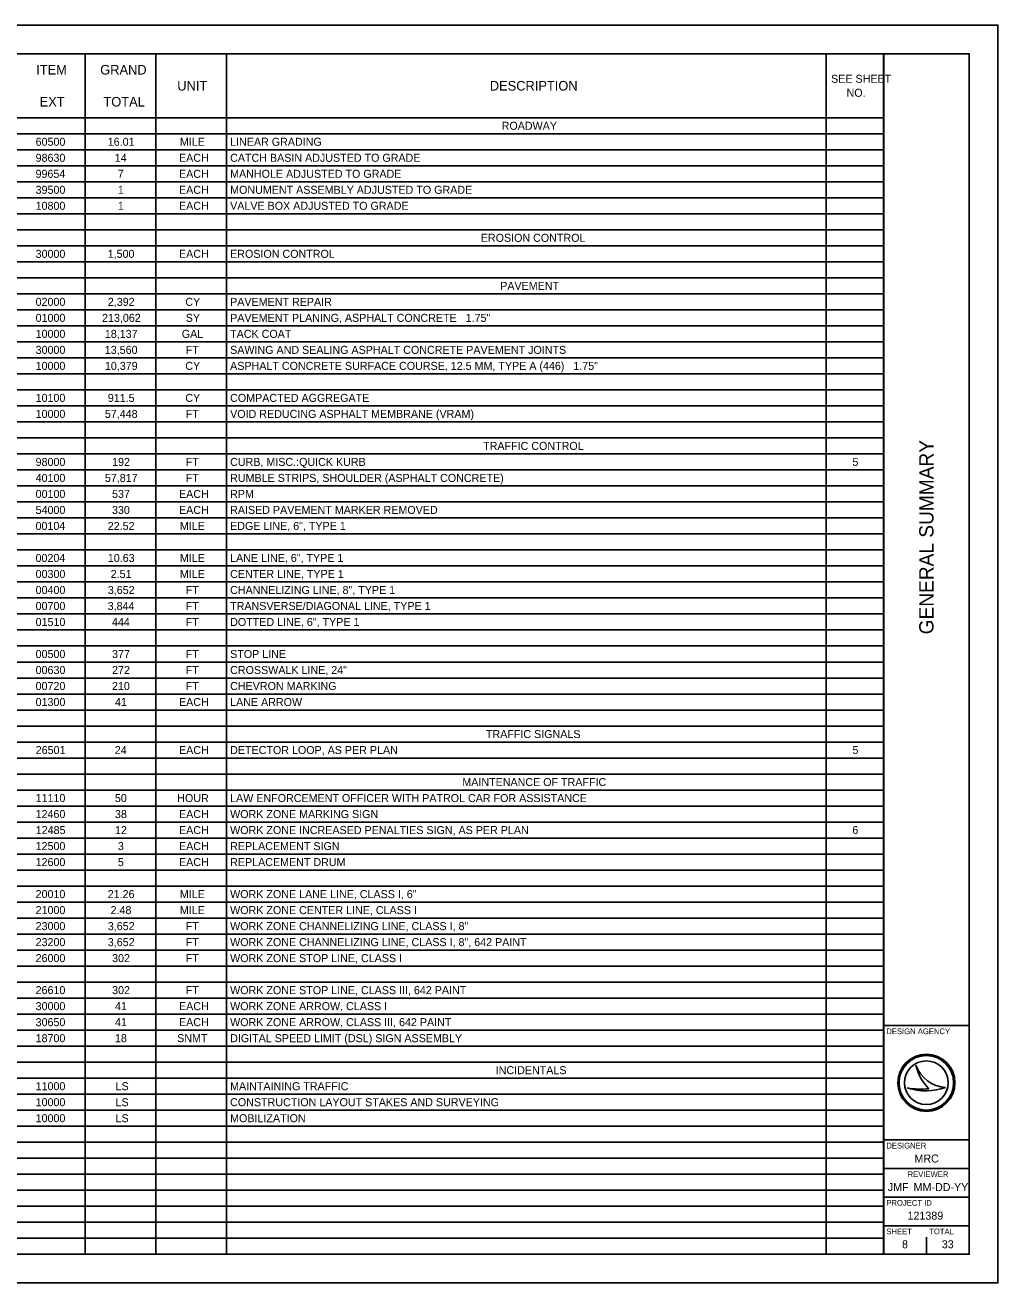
# Model space of a CAD drawing. Extents: x 0 to 34, y 0 to 22.
# Drawn here: x 16.99 to 34, y 0 to 22 of the extents above; entities that cross this region are included whole.
import ezdxf

# ---------------------------------------------------------------- set-up
doc = ezdxf.new("R2010")
doc.units = 0
for name, color, linetype in [('Default', 7, 'Continuous'), ('SH_Border', 7, 'Continuous'), ('SH_Cut_Line', 7, 'Continuous'), ('SH_Data', 7, 'Continuous')]:
    doc.layers.add(name, color=color, linetype=linetype)

msp = doc.modelspace()

# ---------------------------------------------------------------- linework, layer by layer
at = {"layer": 'SH_Border'}
for p, q in [((32, 0.5), (32, 21.5)), ((32, 4.5), (33.5, 4.5)), ((32, 2.5), (33.5, 2.5)), ((32, 2), (33.5, 2)), ((32, 1.5), (33.5, 1.5)), ((32, 1), (33.5, 1))]:
    msp.add_line(p, q, dxfattribs=at)
msp.add_lwpolyline([(1.5, 21.5), (33.5, 21.5), (33.5, 0.5), (1.5, 0.5)], close=True, dxfattribs=at)
at = {"layer": 'SH_Cut_Line'}
msp.add_lwpolyline([(0, 0), (34, 0), (34, 22), (0, 22)], close=True, dxfattribs=at)
at = {"layer": 'SH_Data'}
for p, q in [((1.5, 21.5), (32.004, 21.5)), ((18.036, 21.5), (18.036, 0.5)), ((19.272, 21.5), (19.272, 0.5)), ((20.507, 21.5), (20.507, 0.5)), ((30.999, 21.5), (30.999, 0.5)), ((32.004, 21.5), (32.004, 0.5)), ((1.5, 20.38), (32.004, 20.38)), ((1.5, 20.1), (32.004, 20.1)), ((1.5, 19.82), (32.004, 19.82)), ((1.5, 19.54), (32.004, 19.54)), ((1.5, 19.26), (32.004, 19.26)), ((1.5, 18.98), (32.004, 18.98)), ((1.5, 18.7), (32.004, 18.7)), ((1.5, 18.42), (32.004, 18.42)), ((1.5, 18.14), (32.004, 18.14)), ((1.5, 17.86), (32.004, 17.86)), ((1.5, 17.58), (32.004, 17.58)), ((1.5, 17.3), (32.004, 17.3)), ((1.5, 17.02), (32.004, 17.02)), ((1.5, 16.74), (32.004, 16.74)), ((1.5, 16.46), (32.004, 16.46)), ((1.5, 16.18), (32.004, 16.18)), ((1.5, 15.9), (32.004, 15.9)), ((1.5, 15.62), (32.004, 15.62)), ((1.5, 15.34), (32.004, 15.34)), ((1.5, 15.06), (32.004, 15.06)), ((1.5, 14.78), (32.004, 14.78)), ((1.5, 14.5), (32.004, 14.5)), ((1.5, 14.22), (32.004, 14.22)), ((1.5, 13.94), (32.004, 13.94)), ((1.5, 13.66), (32.004, 13.66)), ((1.5, 13.38), (32.004, 13.38)), ((1.5, 13.1), (32.004, 13.1)), ((1.5, 12.82), (32.004, 12.82)), ((1.5, 12.54), (32.004, 12.54)), ((1.5, 12.26), (32.004, 12.26)), ((1.5, 11.98), (32.004, 11.98)), ((1.5, 11.7), (32.004, 11.7)), ((1.5, 11.42), (32.004, 11.42)), ((1.5, 11.14), (32.004, 11.14)), ((1.5, 10.86), (32.004, 10.86)), ((1.5, 10.58), (32.004, 10.58)), ((1.5, 10.3), (32.004, 10.3)), ((1.5, 10.02), (32.004, 10.02)), ((1.5, 9.74), (32.004, 9.74)), ((1.5, 9.46), (32.004, 9.46)), ((1.5, 9.18), (32.004, 9.18)), ((1.5, 8.9), (32.004, 8.9)), ((1.5, 8.62), (32.004, 8.62)), ((1.5, 8.34), (32.004, 8.34)), ((1.5, 8.06), (32.004, 8.06)), ((1.5, 7.78), (32.004, 7.78)), ((1.5, 7.5), (32.004, 7.5)), ((1.5, 7.22), (32.004, 7.22)), ((1.5, 6.94), (32.004, 6.94)), ((1.5, 6.66), (32.004, 6.66)), ((1.5, 6.38), (32.004, 6.38)), ((1.5, 6.1), (32.004, 6.1)), ((1.5, 5.82), (32.004, 5.82)), ((1.5, 5.54), (32.004, 5.54)), ((1.5, 5.26), (32.004, 5.26)), ((1.5, 4.98), (32.004, 4.98)), ((1.5, 4.7), (32.004, 4.7)), ((1.5, 4.42), (32.004, 4.42)), ((1.5, 4.14), (32.004, 4.14)), ((1.5, 3.86), (32.004, 3.86)), ((32.567, 3.81), (32.567, 3.81)), ((1.5, 3.58), (32.004, 3.58)), ((32.417, 3.41), (32.417, 3.41)), ((32.75, 3.5), (32.75, 3.5)), ((33.087, 3.419), (33.087, 3.419)), ((1.5, 3.3), (32.004, 3.3)), ((1.5, 3.02), (32.004, 3.02)), ((1.5, 2.74), (32.004, 2.74)), ((1.5, 2.46), (32.004, 2.46)), ((1.5, 2.18), (32.004, 2.18)), ((1.5, 1.9), (32.004, 1.9)), ((1.5, 1.62), (32.004, 1.62)), ((1.5, 1.34), (32.004, 1.34)), ((1.5, 1.06), (32.004, 1.06)), ((1.5, 0.78), (32.004, 0.78)), ((32.375, 0.675), (32.375, 0.675)), ((32.75, 0.5), (32.75, 0.8)), ((1.5, 0.5), (32.004, 0.5))]:
    msp.add_line(p, q, dxfattribs=at)
for radius in [0.5, 0.477, 0.477, 0.382]:
    msp.add_circle((32.75, 3.5), radius, dxfattribs=at)
for centre, radius, start, end in [((33.116, 3.998), 0.58, 198.9257, 198.9319), ((33.347, 3.97), 0.796, 191.6379, 191.6421), ((33.116, 3.998), 0.58, 198.9319, 267.1657), ((33.347, 3.97), 0.796, 191.6421, 226.0947), ((32.739, 4.37), 1.013, 251.4576, 290.0832), ((32.648, 4.654), 1.266, 259.4964, 259.4995), ((32.739, 4.37), 1.013, 251.4527, 251.4576), ((32.648, 4.654), 1.266, 259.4995, 276.6672)]:
    msp.add_arc(centre, radius, start, end, dxfattribs=at)

# ---------------------------------------------------------------- texts
at = {"layer": 'Default'}
for s, height, p in [('ITEM', 0.168, (17.181, 21.136)), ('GRAND', 0.168, (18.301, 21.136)), ('SEE SHEET ', 0.14, (31.084, 20.992)), ('UNIT', 0.168, (19.649, 20.856)), ('DESCRIPTION', 0.168, (25.115, 20.856)), ('EXT', 0.168, (17.242, 20.576)), ('TOTAL', 0.168, (18.357, 20.576)), ('NO.', 0.14, (31.354, 20.747)), ('ROADWAY', 0.14, (25.322, 20.17)), ('60500', 0.14, (17.171, 19.89)), ('16.01', 0.14, (18.433, 19.89)), ('MILE', 0.14, (19.695, 19.89)), ('LINEAR GRADING', 0.14, (20.573, 19.89)), ('98630', 0.14, (17.171, 19.61)), ('14', 0.14, (18.556, 19.61)), ('EACH', 0.14, (19.679, 19.61)), ('CATCH BASIN ADJUSTED TO GRADE', 0.14, (20.573, 19.61)), ('99654', 0.14, (17.17, 19.33)), ('7', 0.14, (18.608, 19.33)), ('EACH', 0.14, (19.679, 19.33)), ('MANHOLE ADJUSTED TO GRADE', 0.14, (20.573, 19.33)), ('39500', 0.14, (17.171, 19.05)), ('1', 0.14, (18.609, 19.05)), ('EACH', 0.14, (19.679, 19.05)), ('MONUMENT ASSEMBLY ADJUSTED TO GRADE', 0.14, (20.573, 19.05)), ('10800', 0.14, (17.171, 18.77)), ('1', 0.14, (18.609, 18.77)), ('EACH', 0.14, (19.679, 18.77)), ('VALVE BOX ADJUSTED TO GRADE', 0.14, (20.573, 18.77)), ('EROSION CONTROL', 0.14, (24.957, 18.21)), ('30000', 0.14, (17.171, 17.93)), ('1,500', 0.14, (18.432, 17.93)), ('EACH', 0.14, (19.679, 17.93)), ('EROSION CONTROL', 0.14, (20.573, 17.93)), ('PAVEMENT', 0.14, (25.296, 17.37)), ('02000', 0.14, (17.171, 17.09)), ('2,392', 0.14, (18.434, 17.09)), ('CY', 0.14, (19.79, 17.09)), ('PAVEMENT REPAIR', 0.14, (20.573, 17.09)), ('01000', 0.14, (17.171, 16.81)), ('213,062', 0.14, (18.333, 16.81)), ('SY', 0.14, (19.798, 16.81)), ('PAVEMENT PLANING, ASPHALT CONCRETE   1.75"', 0.14, (20.573, 16.81)), ('10000', 0.14, (17.171, 16.53)), ('18,137', 0.14, (18.382, 16.53)), ('GAL', 0.14, (19.728, 16.53)), ('TACK COAT', 0.14, (20.573, 16.53)), ('30000', 0.14, (17.171, 16.25)), ('13,560', 0.14, (18.381, 16.25)), ('FT', 0.14, (19.796, 16.25)), ('SAWING AND SEALING ASPHALT CONCRETE PAVEMENT JOINTS', 0.14, (20.573, 16.25)), ('10000', 0.14, (17.171, 15.97)), ('10,379', 0.14, (18.383, 15.97)), ('CY', 0.14, (19.79, 15.97)), ('ASPHALT CONCRETE SURFACE COURSE, 12.5 MM, TYPE A (446)   1.75"', 0.14, (20.573, 15.97)), ('10100', 0.14, (17.171, 15.41)), ('911.5', 0.14, (18.434, 15.41)), ('CY', 0.14, (19.79, 15.41)), ('COMPACTED AGGREGATE', 0.14, (20.573, 15.41)), ('10000', 0.14, (17.171, 15.13)), ('57,448', 0.14, (18.382, 15.13)), ('FT', 0.14, (19.796, 15.13)), ('VOID REDUCING ASPHALT MEMBRANE (VRAM)', 0.14, (20.573, 15.13)), ('TRAFFIC CONTROL', 0.14, (24.998, 14.57)), ('98000', 0.14, (17.171, 14.29)), ('192', 0.14, (18.509, 14.29)), ('FT', 0.14, (19.796, 14.29)), ('CURB, MISC.:QUICK KURB', 0.14, (20.573, 14.29)), ('5', 0.14, (31.457, 14.29)), ('40100', 0.14, (17.171, 14.01)), ('57,817', 0.14, (18.382, 14.01)), ('FT', 0.14, (19.796, 14.01)), ('RUMBLE STRIPS, SHOULDER (ASPHALT CONCRETE)', 0.14, (20.573, 14.01)), ('00100', 0.14, (17.171, 13.73)), ('537', 0.14, (18.508, 13.73)), ('EACH', 0.14, (19.679, 13.73)), ('RPM', 0.14, (20.573, 13.73)), ('54000', 0.14, (17.171, 13.45)), ('330', 0.14, (18.507, 13.45)), ('EACH', 0.14, (19.679, 13.45)), ('RAISED PAVEMENT MARKER REMOVED', 0.14, (20.573, 13.45)), ('00104', 0.14, (17.17, 13.17)), ('22.52', 0.14, (18.433, 13.17)), ('MILE', 0.14, (19.695, 13.17)), ('EDGE LINE, 6", TYPE 1', 0.14, (20.573, 13.17)), ('00204', 0.14, (17.17, 12.61)), ('10.63', 0.14, (18.434, 12.61)), ('MILE', 0.14, (19.695, 12.61)), ('LANE LINE, 6", TYPE 1', 0.14, (20.573, 12.61)), ('00300', 0.14, (17.171, 12.33)), ('2.51', 0.14, (18.484, 12.33)), ('MILE', 0.14, (19.695, 12.33)), ('CENTER LINE, TYPE 1', 0.14, (20.573, 12.33)), ('00400', 0.14, (17.171, 12.05)), ('3,652', 0.14, (18.434, 12.05)), ('FT', 0.14, (19.796, 12.05)), ('CHANNELIZING LINE, 8", TYPE 1', 0.14, (20.573, 12.05)), ('00700', 0.14, (17.171, 11.77)), ('3,844', 0.14, (18.431, 11.77)), ('FT', 0.14, (19.796, 11.77)), ('TRANSVERSE/DIAGONAL LINE, TYPE 1', 0.14, (20.573, 11.77)), ('01510', 0.14, (17.171, 11.49)), ('444', 0.14, (18.506, 11.49)), ('FT', 0.14, (19.796, 11.49)), ('DOTTED LINE, 6", TYPE 1', 0.14, (20.573, 11.49)), ('00500', 0.14, (17.171, 10.93)), ('377', 0.14, (18.508, 10.93)), ('FT', 0.14, (19.796, 10.93)), ('STOP LINE', 0.14, (20.573, 10.93)), ('00630', 0.14, (17.171, 10.65)), ('272', 0.14, (18.509, 10.65)), ('FT', 0.14, (19.796, 10.65)), ('CROSSWALK LINE, 24"', 0.14, (20.573, 10.65)), ('00720', 0.14, (17.171, 10.37)), ('210', 0.14, (18.507, 10.37)), ('FT', 0.14, (19.796, 10.37)), ('CHEVRON MARKING', 0.14, (20.573, 10.37)), ('01300', 0.14, (17.171, 10.09)), ('41', 0.14, (18.559, 10.09)), ('EACH', 0.14, (19.679, 10.09)), ('LANE ARROW', 0.14, (20.573, 10.09)), ('TRAFFIC SIGNALS', 0.14, (25.047, 9.53)), ('26501', 0.14, (17.173, 9.25)), ('24', 0.14, (18.556, 9.25)), ('EACH', 0.14, (19.679, 9.25)), ('DETECTOR LOOP, AS PER PLAN', 0.14, (20.573, 9.25)), ('5', 0.14, (31.457, 9.25)), ('MAINTENANCE OF TRAFFIC', 0.14, (24.634, 8.69)), ('11110', 0.14, (17.171, 8.41)), ('50', 0.14, (18.557, 8.41)), ('HOUR', 0.14, (19.648, 8.41)), ('LAW ENFORCEMENT OFFICER WITH PATROL CAR FOR ASSISTANCE', 0.14, (20.573, 8.41)), ('12460', 0.14, (17.171, 8.13)), ('38', 0.14, (18.558, 8.13)), ('EACH', 0.14, (19.679, 8.13)), ('WORK ZONE MARKING SIGN', 0.14, (20.573, 8.13)), ('12485', 0.14, (17.173, 7.85)), ('12', 0.14, (18.559, 7.85)), ('EACH', 0.14, (19.679, 7.85)), ('WORK ZONE INCREASED PENALTIES SIGN, AS PER PLAN', 0.14, (20.573, 7.85)), ('6', 0.14, (31.455, 7.85)), ('12500', 0.14, (17.171, 7.57)), ('3', 0.14, (18.61, 7.57)), ('EACH', 0.14, (19.679, 7.57)), ('REPLACEMENT SIGN', 0.14, (20.573, 7.57)), ('12600', 0.14, (17.171, 7.29)), ('5', 0.14, (18.61, 7.29)), ('EACH', 0.14, (19.679, 7.29)), ('REPLACEMENT DRUM', 0.14, (20.573, 7.29)), ('20010', 0.14, (17.171, 6.73)), ('21.26', 0.14, (18.432, 6.73)), ('MILE', 0.14, (19.695, 6.73)), ('WORK ZONE LANE LINE, CLASS I, 6"', 0.14, (20.573, 6.73)), ('21000', 0.14, (17.171, 6.45)), ('2.48', 0.14, (18.482, 6.45)), ('MILE', 0.14, (19.695, 6.45)), ('WORK ZONE CENTER LINE, CLASS I', 0.14, (20.573, 6.45)), ('23000', 0.14, (17.171, 6.17)), ('3,652', 0.14, (18.434, 6.17)), ('FT', 0.14, (19.796, 6.17)), ('WORK ZONE CHANNELIZING LINE, CLASS I, 8"', 0.14, (20.573, 6.17)), ('23200', 0.14, (17.171, 5.89)), ('3,652', 0.14, (18.434, 5.89)), ('FT', 0.14, (19.796, 5.89)), ('WORK ZONE CHANNELIZING LINE, CLASS I, 8", 642 PAINT', 0.14, (20.573, 5.89)), ('26000', 0.14, (17.171, 5.61)), ('302', 0.14, (18.509, 5.61)), ('FT', 0.14, (19.796, 5.61)), ('WORK ZONE STOP LINE, CLASS I', 0.14, (20.573, 5.61)), ('26610', 0.14, (17.171, 5.05)), ('302', 0.14, (18.509, 5.05)), ('FT', 0.14, (19.796, 5.05)), ('WORK ZONE STOP LINE, CLASS III, 642 PAINT', 0.14, (20.573, 5.05)), ('30000', 0.14, (17.171, 4.77)), ('41', 0.14, (18.559, 4.77)), ('EACH', 0.14, (19.679, 4.77)), ('WORK ZONE ARROW, CLASS I', 0.14, (20.573, 4.77)), ('30650', 0.14, (17.171, 4.49)), ('41', 0.14, (18.559, 4.49)), ('EACH', 0.14, (19.679, 4.49)), ('WORK ZONE ARROW, CLASS III, 642 PAINT', 0.14, (20.573, 4.49)), ('18700', 0.14, (17.171, 4.21)), ('18', 0.14, (18.558, 4.21)), ('SNMT', 0.14, (19.647, 4.21)), ('DIGITAL SPEED LIMIT (DSL) SIGN ASSEMBLY', 0.14, (20.573, 4.21)), ('INCIDENTALS', 0.14, (25.218, 3.65)), ('11000', 0.14, (17.171, 3.37)), ('LS', 0.14, (18.57, 3.37)), ('MAINTAINING TRAFFIC', 0.14, (20.573, 3.37)), ('10000', 0.14, (17.171, 3.09)), ('LS', 0.14, (18.57, 3.09)), ('CONSTRUCTION LAYOUT STAKES AND SURVEYING', 0.14, (20.573, 3.09)), ('10000', 0.14, (17.171, 2.81)), ('LS', 0.14, (18.57, 2.81)), ('MOBILIZATION', 0.14, (20.573, 2.81))]:
    msp.add_text(s, height=height, dxfattribs=at).set_placement(p)
at = {"layer": 'SH_Data'}
msp.add_text('GENERAL SUMMARY', height=0.25, rotation=90, dxfattribs=at).set_placement((32.875, 11.344))
for s, height, p in [('DESIGN AGENCY', 0.1, (32.05, 4.35)), ('DESIGNER', 0.1, (32.05, 2.35)), ('MRC', 0.14, (32.541, 2.105)), ('REVIEWER', 0.1, (32.422, 1.85)), ('JMF', 0.14, (32.075, 1.605)), ('MM-DD-YY', 0.14, (32.527, 1.605)), ('PROJECT ID', 0.1, (32.05, 1.35)), ('121389', 0.14, (32.42, 1.105)), ('SHEET', 0.1, (32.05, 0.85)), ('TOTAL', 0.1, (32.8, 0.85)), ('8', 0.14, (32.324, 0.605)), ('33', 0.14, (33.02, 0.605))]:
    msp.add_text(s, height=height, dxfattribs=at).set_placement(p)

doc.saveas('drawing.dxf')
